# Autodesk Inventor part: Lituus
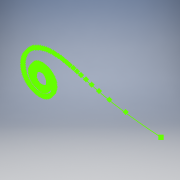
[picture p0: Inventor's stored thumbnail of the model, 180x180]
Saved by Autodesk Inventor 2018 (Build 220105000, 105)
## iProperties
Created: 2008-02
Part Number: Lituus
Document SubType Name: Modeling
Designer: Autodesk, Inc.
Density: 1 g/cm^3
Material: Generic
Appearance: Default
Author: Autodesk, Inc.
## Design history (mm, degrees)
sketch "Sketch1"
  geometry: 300 further points
  constraints: 300 other
